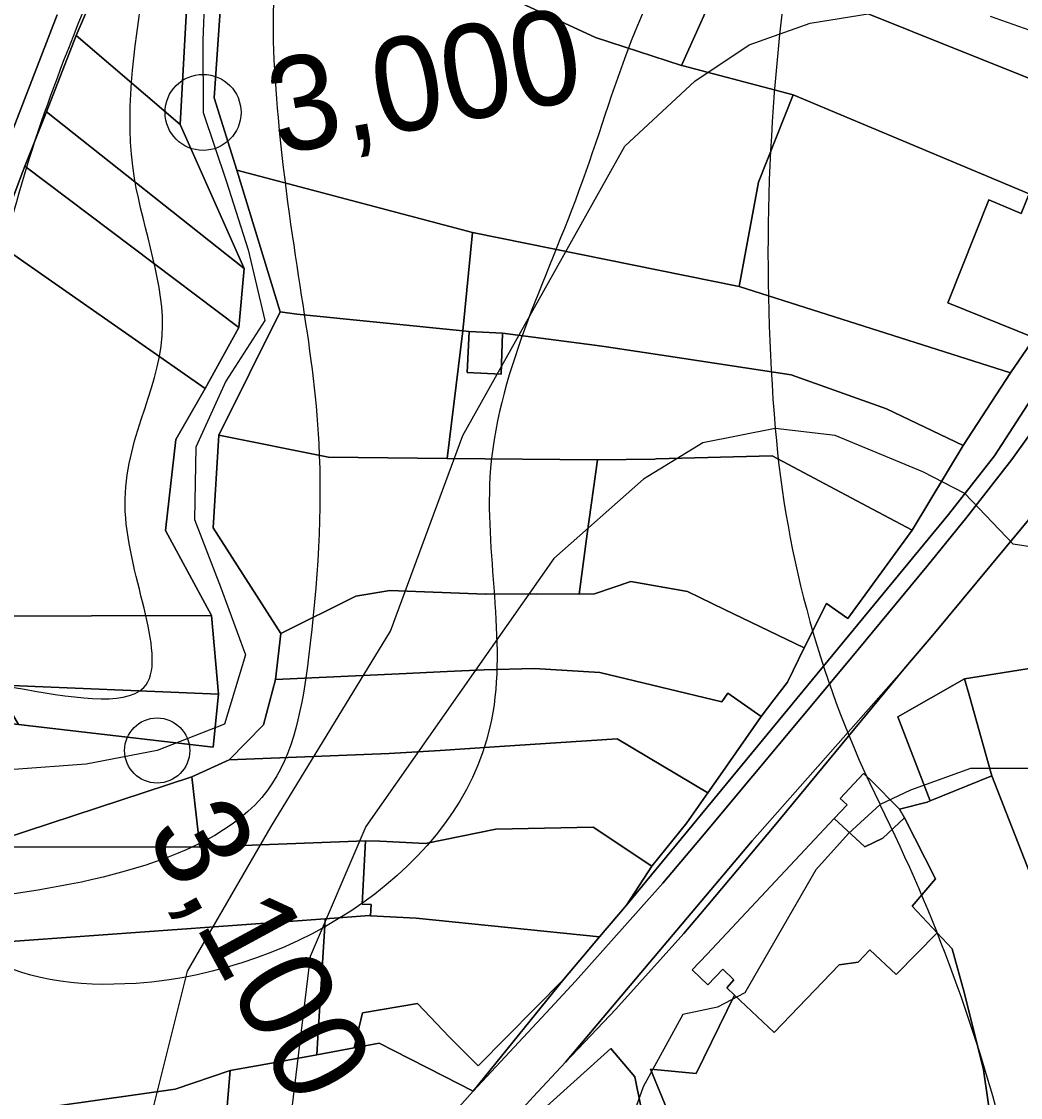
# Model space of a CAD drawing. Extents: x -510989 to -501240, y -1184665 to -1176098.
# Drawn here: x -504823 to -504684.9, y -1182308.5 to -1182159.8 of the extents above; entities that cross this region are included whole.
import ezdxf

# ---------------------------------------------------------------- set-up
doc = ezdxf.new("R2010")
doc.units = 0
for name, color, linetype in [('NAVRH_rozvodnice', 7, 'Continuous'), ('ostatni_plocha_x_draha', 7, 'Continuous'), ('ostatni_plocha_x_neplodna_puda', 7, 'Continuous'), ('ostatni_plocha_x_ostatni_komunikace', 7, 'Continuous'), ('ostatni_plocha_x_silnice', 7, 'Continuous'), ('STAV_zaplavove_uzemi', 7, 'Continuous'), ('trasovani_toku', 7, 'Continuous'), ('trvaly_travni_porost', 7, 'Continuous'), ('vodni_plocha_x_vodni_tok_v_koryt_prir_n_upr', 7, 'Continuous'), ('vrstevnice_01', 7, 'Continuous'), ('vrstevnice_02', 7, 'Continuous'), ('zahrada', 7, 'Continuous'), ('zastavena_plocha_a_nadvori', 7, 'Continuous')]:
    doc.layers.add(name, color=color, linetype=linetype)

msp = doc.modelspace()

# ---------------------------------------------------------------- linework, layer by layer
at = {"layer": 'NAVRH_rozvodnice'}
for centre, radius, start, end in [((-504430.33, -1182191.97), 289.48, 159.1879, 184.7617), ((-504575.51, -1182204.06), 143.79, 184.7617, 206.4002), ((-504915.08, -1182372.63), 235.31, 13.925, 26.4002)]:
    msp.add_arc(centre, radius, start, end, dxfattribs=at)
at = {"layer": 'ostatni_plocha_x_draha'}
msp.add_lwpolyline([(-504818.09, -1182158.83), (-504829.87, -1182189.28), (-504837.58, -1182231.95), (-504833.33, -1182254.08), (-504832.95, -1182255.81), (-504828.96, -1182273.83), (-504828.71, -1182274.97), (-504833.19, -1182275.82), (-504832.22, -1182287.45), (-504829.16, -1182311.19), (-504827.78, -1182318.57), (-504818.47, -1182369.92), (-504825.21, -1182377.61), (-504825.27, -1182384.49), (-504825.8, -1182395.57), (-504822.32, -1182398.72), (-504811.75, -1182408.26), (-504817.08, -1182415.24), (-504816.58, -1182438.27), (-504816.44, -1182444.56), (-504814.64, -1182480.22)], dxfattribs=at)
at = {"layer": 'ostatni_plocha_x_neplodna_puda'}
msp.add_lwpolyline([(-504694.34, -1182287.92), (-504692.64, -1182294.12), (-504690.01, -1182304.64), (-504686.8, -1182326.98), (-504702.57, -1182329.09), (-504718.84, -1182331.27), (-504724.73, -1182332.06), (-504736.04, -1182304.55), (-504729.74, -1182305.15), (-504724.43, -1182294.34), (-504718.94, -1182299.49), (-504709.99, -1182290.13), (-504707.35, -1182289.77), (-504705.71, -1182288.06), (-504702.09, -1182291.48), (-504696.41, -1182285.71)], close=True, dxfattribs=at)
at = {"layer": 'ostatni_plocha_x_ostatni_komunikace'}
for points in [[(-504804.88, -1182137.1), (-504815.47, -1182161.68), (-504819.56, -1182172.23), (-504822.57, -1182179.77), (-504826.57, -1182190.32), (-504832.12, -1182217.73), (-504833.01, -1182222.27), (-504830, -1182241.97), (-504826.67, -1182251.43), (-504823.42, -1182256.92), (-504832.95, -1182255.81), (-504833.33, -1182254.08), (-504837.58, -1182231.95), (-504829.87, -1182189.28), (-504818.09, -1182158.83)], [(-504683.43, -1182211.95), (-504688.49, -1182219.81), (-504694.87, -1182227.88), (-504739.37, -1182281.88), (-504735.89, -1182276.48), (-504731.02, -1182270.51), (-504728.15, -1182266.37), (-504726.37, -1182263.87), (-504720.77, -1182255.81), (-504719, -1182253.51), (-504717.1, -1182251.06), (-504714.82, -1182246.33), (-504711.74, -1182240.21), (-504708.78, -1182242.26), (-504699.89, -1182230.04), (-504692.84, -1182218.37), (-504686.3, -1182208.31), (-504682.98, -1182203.49)], [(-504756.37, -1182312.89), (-504752.28, -1182308.37), (-504747.79, -1182303.57), (-504740.85, -1182296.26), (-504731.46, -1182285.8), (-504728.12, -1182281.9), (-504718.97, -1182270.95), (-504701.01, -1182249.26), (-504697.03, -1182244.56), (-504682.84, -1182227.46)], [(-504678.47, -1182248.35), (-504692.63, -1182250.62), (-504701.87, -1182255.88), (-504697.4, -1182267.48), (-504697.8, -1182267.64), (-504701.61, -1182268.61), (-504705.64, -1182264.56), (-504706.59, -1182263.67), (-504709.82, -1182267.13), (-504708.87, -1182268.02), (-504710.64, -1182269.92), (-504728.23, -1182288.67), (-504730.28, -1182290.81), (-504728.12, -1182292.89), (-504726.04, -1182290.73), (-504724.53, -1182292.19), (-504725.5, -1182293.33), (-504724.43, -1182294.34), (-504729.74, -1182305.15), (-504736.04, -1182304.55), (-504724.73, -1182332.06)], [(-504735.83, -1182317.48), (-504738.22, -1182305.62), (-504741.53, -1182301.68), (-504750.38, -1182309.69)]]:
    msp.add_lwpolyline(points, dxfattribs=at)
at = {"layer": 'ostatni_plocha_x_silnice'}
for points in [[(-504766.11, -1182313.77), (-504760.55, -1182307.61), (-504749.86, -1182296.14), (-504746.43, -1182292.4), (-504737.71, -1182282.64), (-504734.35, -1182278.85), (-504728.65, -1182272.06), (-504708.46, -1182247.87), (-504697.85, -1182235.08), (-504692.31, -1182228.28), (-504686.08, -1182220.29), (-504681.44, -1182213.79), (-504676.25, -1182205.38), (-504672.53, -1182198), (-504670.11, -1182192.37), (-504668.31, -1182187.63), (-504666.07, -1182180.74), (-504664.83, -1182175.8), (-504663.05, -1182167.12), (-504660.74, -1182161.27), (-504660.37, -1182149.27)], [(-504654.43, -1182155.52), (-504655.64, -1182163.51), (-504656.9, -1182170.57), (-504658.17, -1182176.68), (-504659.83, -1182183.78), (-504669.04, -1182203.7), (-504682.84, -1182227.46), (-504697.03, -1182244.56), (-504701.01, -1182249.26), (-504722, -1182272.99), (-504747.79, -1182303.57), (-504752.28, -1182308.37), (-504756.37, -1182312.89)], [(-504681.44, -1182213.79), (-504686.08, -1182220.29), (-504692.31, -1182228.28), (-504697.85, -1182235.08), (-504708.46, -1182247.87), (-504728.65, -1182272.06), (-504734.35, -1182278.85), (-504737.71, -1182282.64), (-504746.43, -1182292.4), (-504749.86, -1182296.14), (-504760.55, -1182307.61), (-504748.02, -1182292.13), (-504743.1, -1182286.27), (-504739.37, -1182281.88), (-504694.87, -1182227.88), (-504688.49, -1182219.81), (-504683.43, -1182211.95)]]:
    msp.add_lwpolyline(points, dxfattribs=at)
msp.add_lwpolyline([(-504701.01, -1182249.26), (-504718.97, -1182270.95), (-504728.12, -1182281.9), (-504731.46, -1182285.8), (-504740.85, -1182296.26), (-504747.79, -1182303.57), (-504722, -1182272.99)], close=True, dxfattribs=at)
at = {"layer": 'STAV_zaplavove_uzemi'}
for points in [[(-504826.46, -1182247.73), (-504827.62, -1182204.68), (-504817.15, -1182165.12), (-504791.55, -1182113.93), (-504727.56, -1182034.81), (-504708.94, -1182017.35), (-504669.38, -1181991.76), (-504649.6, -1181961.5), (-504628.66, -1181917.29), (-504601.9, -1181867.26), (-504597.24, -1181809.08), (-504585.16, -1181766.79), (-504596.8, -1181741.4), (-504604.2, -1181726.59), (-504633.82, -1181658.9), (-504646.51, -1181600.72), (-504660.26, -1181556.29), (-504751.04, -1181459.08), (-504798.4, -1181384.84), (-504826.55, -1181347.73), (-504862.39, -1181315.73), (-504866.23, -1181265.81), (-504862.39, -1181205.66), (-504853.43, -1181164.7), (-504793.92, -1181116.47), (-504755.84, -1181064.64), (-504725.17, -1181018.1), (-504649.01, -1180947.23), (-504594, -1180900.69), (-504545.35, -1180879.53), (-504377.38, -1180832.83), (-504317.01, -1180808.36), (-504368.93, -1180802.59), (-504426.63, -1180826.63), (-504542.02, -1180859.32)], [(-504547.82, -1181597.63), (-504529.08, -1181677.7), (-504510.34, -1181762.87), (-504510.34, -1181805.46), (-504503.52, -1181848.05), (-504522.26, -1181902.56), (-504557.31, -1181989.81), (-504582.91, -1182010.28), (-504608.51, -1182029.48), (-504618.75, -1182071.72), (-504632.83, -1182096.04), (-504648.18, -1182115.24), (-504664.82, -1182122.91), (-504685.3, -1182130.59), (-504727.54, -1182144.67), (-504745.46, -1182181.79), (-504758.25, -1182222.75), (-504758.25, -1182257.3), (-504807.19, -1182292.7), (-504828.34, -1182288.47), (-504827.28, -1182244.04)], [(-504574.97, -1181692.93), (-504558.07, -1181754.88), (-504562.29, -1181804.15), (-504563.7, -1181856.24), (-504570.74, -1181913.97), (-504583.41, -1181961.83), (-504617.2, -1182002.66), (-504652.4, -1182051.94), (-504665.07, -1182080.1), (-504696.04, -1182099.81), (-504738.28, -1182108.25), (-504752.36, -1182122.33), (-504767.85, -1182144.86), (-504780.52, -1182142.04), (-504787.55, -1182173.02), (-504781.92, -1182218.07), (-504783.33, -1182247.63), (-504788.96, -1182265.94), (-504808.67, -1182277.2), (-504832.61, -1182281.42)], [(-504824.03, -1182251.79), (-504806.11, -1182251.79), (-504808.67, -1182227.48), (-504803.55, -1182203.16), (-504807.39, -1182181.4), (-504806.11, -1182154.52), (-504795.88, -1182126.36), (-504783.08, -1182119.97), (-504770.28, -1182113.56), (-504754.92, -1182091.81), (-504726.76, -1182079.01), (-504689.64, -1182070.05), (-504667.89, -1182041.89), (-504634.61, -1181997.1), (-504615.41, -1181959.98), (-504602.61, -1181927.98), (-504596.21, -1181880.63), (-504594.68, -1181823.86), (-504583.41, -1181774.59), (-504590.45, -1181740.8), (-504600.31, -1181726.72)]]:
    msp.add_spline(points, degree=3, dxfattribs=at)
at = {"layer": 'trasovani_toku'}
for p, q in [((-504797.57, -1182152.33), (-504797.94, -1182162.32)), ((-504797.94, -1182162.32), (-504797.92, -1182172.32)), ((-504797.92, -1182172.32), (-504794.74, -1182181.8)), ((-504794.74, -1182181.8), (-504791.66, -1182191.32)), ((-504791.66, -1182191.32), (-504789.4, -1182201.06)), ((-504789.4, -1182201.06), (-504794.78, -1182209.49)), ((-504794.78, -1182209.49), (-504798.94, -1182218.58)), ((-504798.94, -1182218.58), (-504799.1, -1182228.58)), ((-504799.1, -1182228.58), (-504795.5, -1182237.91)), ((-504795.5, -1182237.91), (-504792.06, -1182247.3)), ((-504792.06, -1182247.3), (-504794.96, -1182256.87)), ((-504794.96, -1182256.87), (-504804.27, -1182260.52)), ((-504804.27, -1182260.52), (-504814.09, -1182262.41)), ((-504814.09, -1182262.41), (-504824.06, -1182263.12))]:
    msp.add_line(p, q, dxfattribs=at)
for centre, radius in [((-504797.92, -1182172.32), 5.25), ((-504804.27, -1182260.52), 4.5)]:
    msp.add_circle(centre, radius, dxfattribs=at)
at = {"layer": 'trvaly_travni_porost'}
for points in [[(-504793.26, -1182112.23), (-504779.73, -1182122.83), (-504769.89, -1182130.23), (-504782.59, -1182127.22), (-504790.34, -1182129.48), (-504796.78, -1182140.31), (-504799.68, -1182148.82), (-504801.08, -1182173.98), (-504815.47, -1182161.68), (-504804.88, -1182137.1)], [(-504819.56, -1182172.23), (-504815.47, -1182161.68), (-504801.08, -1182173.98), (-504792.25, -1182193.9)], [(-504822.57, -1182179.77), (-504819.56, -1182172.23), (-504792.25, -1182193.9), (-504792.98, -1182202.05)], [(-504826.57, -1182190.32), (-504822.57, -1182179.77), (-504792.98, -1182202.05), (-504797.61, -1182210.46)], [(-504826.57, -1182190.32), (-504797.61, -1182210.46), (-504801.69, -1182217.53), (-504803.1, -1182230.12), (-504796.75, -1182241.85), (-504830, -1182241.97), (-504833.01, -1182222.27), (-504832.12, -1182217.73)], [(-504830, -1182241.97), (-504796.75, -1182241.85), (-504795.78, -1182252.73), (-504826.67, -1182251.43)], [(-504795.78, -1182252.73), (-504796.53, -1182260.05), (-504823.42, -1182256.92), (-504826.67, -1182251.43)]]:
    msp.add_lwpolyline(points, close=True, dxfattribs=at)
at = {"layer": 'vodni_plocha_x_vodni_tok_v_koryt_prir_n_upr'}
msp.add_lwpolyline([(-504794.87, -1182148.24), (-504796.39, -1182170.3), (-504793.27, -1182180.29), (-504787.25, -1182199.87), (-504795.75, -1182216.93), (-504796.5, -1182229.75), (-504787.17, -1182244.36), (-504787.92, -1182250.71), (-504789.54, -1182256.96), (-504794.33, -1182261.82), (-504799.48, -1182264.16), (-504828.96, -1182273.83), (-504832.95, -1182255.81), (-504823.42, -1182256.92), (-504796.53, -1182260.05), (-504795.78, -1182252.73), (-504796.75, -1182241.85), (-504803.1, -1182230.12), (-504801.69, -1182217.53), (-504797.61, -1182210.46), (-504792.98, -1182202.05), (-504792.25, -1182193.9), (-504801.08, -1182173.98), (-504799.68, -1182148.82)], dxfattribs=at)
at = {"layer": 'vrstevnice_01'}
msp.add_lwpolyline([(-504613, -1182249), (-504624, -1182240), (-504631.5, -1182236), (-504635.5, -1182235), (-504645.59, -1182237), (-504660, -1182236), (-504685.91, -1182232), (-504692.59, -1182225), (-504698.41, -1182222), (-504710.5, -1182217), (-504718.81, -1182216), (-504728.81, -1182218), (-504737, -1182223), (-504749.41, -1182234), (-504775.41, -1182271), (-504783.09, -1182289), (-504788.69, -1182335)], dxfattribs=at)
at = {"layer": 'vrstevnice_02'}
for points in [[(-504689.09, -1182159), (-504675, -1182164), (-504667.91, -1182167), (-504658.19, -1182176), (-504647.91, -1182178), (-504643.5, -1182184), (-504639.81, -1182187), (-504633.81, -1182189), (-504629.69, -1182188), (-504624.81, -1182186), (-504617.81, -1182180), (-504614.31, -1182172), (-504610.69, -1182153)], [(-504823.59, -1182345), (-504819.91, -1182358), (-504818.59, -1182360), (-504816.59, -1182361), (-504814, -1182361), (-504811.41, -1182357), (-504808.41, -1182347), (-504805.81, -1182325), (-504805.31, -1182312), (-504800.09, -1182291), (-504788.5, -1182271), (-504772, -1182244), (-504762, -1182217), (-504739.59, -1182177), (-504729.91, -1182168), (-504722.41, -1182163), (-504714, -1182160), (-504701.69, -1182158)], [(-504602.41, -1182291), (-504623.69, -1182274), (-504627.81, -1182274), (-504633.19, -1182275), (-504635.69, -1182275), (-504675.5, -1182263), (-504691.81, -1182263), (-504700.09, -1182266), (-504704.31, -1182268), (-504708.69, -1182272), (-504713.19, -1182277), (-504723, -1182294), (-504726.81, -1182296), (-504731.59, -1182297), (-504737.09, -1182307), (-504738.5, -1182311), (-504739.41, -1182328)]]:
    msp.add_lwpolyline(points, dxfattribs=at)
at = {"layer": 'zahrada'}
for points in [[(-504783.29, -1182133.37), (-504777.16, -1182133.05), (-504769.3, -1182135.01), (-504736.9, -1182149.9), (-504726, -1182152.98), (-504731.77, -1182165.83), (-504743.64, -1182161.96), (-504791.97, -1182139.62), (-504787.17, -1182134.66)], [(-504791.97, -1182139.62), (-504743.64, -1182161.96), (-504731.77, -1182165.83), (-504731.55, -1182165.9), (-504716.35, -1182169.88), (-504721.13, -1182181.96), (-504723.8, -1182196.37), (-504760.65, -1182188.91), (-504793.27, -1182180.29), (-504796.39, -1182170.3), (-504794.87, -1182148.24)], [(-504793.27, -1182180.29), (-504760.65, -1182188.91), (-504762, -1182202.53), (-504784.94, -1182200.19), (-504787.25, -1182199.87)], [(-504723.8, -1182196.37), (-504686.3, -1182208.31), (-504692.84, -1182218.37), (-504703.44, -1182213.28), (-504716.62, -1182208.58), (-504733.56, -1182206.02), (-504742.16, -1182204.72), (-504743.78, -1182204.47), (-504756.51, -1182202.84), (-504761.12, -1182202.62), (-504762, -1182202.53), (-504760.65, -1182188.91)], [(-504787.25, -1182199.87), (-504784.94, -1182200.19), (-504762, -1182202.53), (-504764.17, -1182220.16), (-504780.58, -1182219.97), (-504795.75, -1182216.93)], [(-504780.58, -1182219.97), (-504764.17, -1182220.16), (-504743.38, -1182220.33), (-504744.79, -1182230.59), (-504745.93, -1182238.92), (-504751.83, -1182238.86), (-504758.81, -1182238.89), (-504758.87, -1182238.89), (-504772.09, -1182238.39), (-504776.79, -1182239.17), (-504787.17, -1182244.36), (-504796.5, -1182229.75), (-504795.75, -1182216.93)], [(-504692.63, -1182250.62), (-504691.95, -1182253.01), (-504689.35, -1182262.23), (-504688.84, -1182264.02), (-504697.4, -1182267.48), (-504701.87, -1182255.88)], [(-504799.48, -1182264.16), (-504798.37, -1182273.87), (-504828.96, -1182273.83)], [(-504798.37, -1182273.87), (-504775.44, -1182273.01), (-504775.91, -1182281.73), (-504774.69, -1182281.81), (-504774.78, -1182283.35), (-504774.92, -1182283.34), (-504781.03, -1182283.8), (-504832.22, -1182287.45), (-504833.19, -1182275.82), (-504828.71, -1182274.97), (-504828.96, -1182273.83)], [(-504781.09, -1182284.77), (-504782.03, -1182300.18), (-504782.18, -1182302.56), (-504788.44, -1182303.71), (-504794.15, -1182304.76), (-504801.77, -1182307.31), (-504829.16, -1182311.19), (-504832.22, -1182287.45), (-504781.03, -1182283.8)], [(-504775.89, -1182296.77), (-504768.25, -1182295.47), (-504763.85, -1182300.14), (-504759.88, -1182304.08), (-504748.02, -1182292.13), (-504760.55, -1182307.61), (-504764.65, -1182305.53), (-504771.6, -1182301.99), (-504773.58, -1182300.98), (-504777.03, -1182301.61)], [(-504794.15, -1182304.76), (-504794.69, -1182310.8), (-504795.82, -1182316.65), (-504810.79, -1182317.05), (-504827.78, -1182318.57), (-504829.16, -1182311.19), (-504801.77, -1182307.31)]]:
    msp.add_lwpolyline(points, close=True, dxfattribs=at)
at = {"layer": 'zastavena_plocha_a_nadvori'}
for points in [[(-504711.71, -1182141.93), (-504701.67, -1182146.31), (-504695.74, -1182148.63), (-504695.54, -1182148.01), (-504687.85, -1182150.74), (-504687.76, -1182150.51), (-504687.55, -1182149.95), (-504668.12, -1182157.54), (-504668.31, -1182158.11), (-504666.96, -1182158.74), (-504666.17, -1182159.11), (-504668.4, -1182164.75), (-504669.53, -1182164.28), (-504672.79, -1182171.96), (-504694, -1182163.49), (-504705.94, -1182158.72), (-504715.12, -1182155.48), (-504715.65, -1182155.38)], [(-504726, -1182152.98), (-504715.65, -1182155.38), (-504715.12, -1182155.48), (-504705.94, -1182158.72), (-504694, -1182163.49), (-504672.79, -1182171.96), (-504676.92, -1182181.68), (-504678.6, -1182185.63), (-504683.69, -1182183.57), (-504716.35, -1182169.88), (-504731.55, -1182165.9), (-504731.77, -1182165.83)], [(-504721.13, -1182181.96), (-504716.35, -1182169.88), (-504683.69, -1182183.57), (-504684.8, -1182186.31), (-504689.28, -1182184.41), (-504694.94, -1182198.66), (-504682.98, -1182203.49), (-504686.3, -1182208.31), (-504723.8, -1182196.37)], [(-504683.69, -1182183.57), (-504678.6, -1182185.63), (-504676.16, -1182186.61), (-504682.98, -1182203.49), (-504694.94, -1182198.66), (-504689.28, -1182184.41), (-504684.8, -1182186.31)], [(-504762, -1182202.53), (-504761.12, -1182202.62), (-504761.39, -1182208.25), (-504756.71, -1182208.48), (-504756.51, -1182202.84), (-504743.78, -1182204.47), (-504742.16, -1182204.72), (-504733.56, -1182206.02), (-504716.62, -1182208.58), (-504703.44, -1182213.28), (-504692.84, -1182218.37), (-504699.89, -1182230.04), (-504705.34, -1182227.16), (-504719.22, -1182219.81), (-504735.25, -1182220.22), (-504735.45, -1182220.23), (-504743.38, -1182220.33), (-504764.17, -1182220.16)], [(-504761.12, -1182202.62), (-504756.51, -1182202.84), (-504756.71, -1182208.48), (-504761.39, -1182208.25)], [(-504735.25, -1182220.22), (-504719.22, -1182219.81), (-504705.34, -1182227.16), (-504699.89, -1182230.04), (-504708.78, -1182242.26), (-504711.74, -1182240.21), (-504714.82, -1182246.33), (-504725.84, -1182241.01), (-504730.94, -1182238.55), (-504738.79, -1182237.16), (-504743.78, -1182238.88), (-504745.93, -1182238.92), (-504744.79, -1182230.59), (-504743.38, -1182220.33), (-504735.45, -1182220.23)], [(-504738.79, -1182237.16), (-504730.94, -1182238.55), (-504725.84, -1182241.01), (-504714.82, -1182246.33), (-504717.1, -1182251.06), (-504719, -1182253.51), (-504720.77, -1182255.81), (-504725.37, -1182252.61), (-504726.2, -1182253.8), (-504743.06, -1182249.74), (-504752.11, -1182249.19), (-504759.03, -1182249.35), (-504764.18, -1182249.59), (-504770.8, -1182249.9), (-504787.92, -1182250.71), (-504787.17, -1182244.36), (-504776.79, -1182239.17), (-504772.09, -1182238.39), (-504758.87, -1182238.89), (-504758.81, -1182238.89), (-504751.83, -1182238.86), (-504745.93, -1182238.92), (-504743.78, -1182238.88)], [(-504678.47, -1182248.35), (-504677.55, -1182251.26), (-504668.96, -1182277.25), (-504670.23, -1182277.56), (-504676.03, -1182278.97), (-504682.43, -1182280.53), (-504688.84, -1182264.02), (-504689.35, -1182262.23), (-504691.95, -1182253.01), (-504692.63, -1182250.62)], [(-504752.11, -1182249.19), (-504743.06, -1182249.74), (-504726.2, -1182253.8), (-504725.37, -1182252.61), (-504720.77, -1182255.81), (-504726.37, -1182263.87), (-504728.15, -1182266.37), (-504740.66, -1182258.88), (-504756.94, -1182259.97), (-504765.14, -1182260.5), (-504772.18, -1182260.93), (-504794.33, -1182261.82), (-504789.54, -1182256.96), (-504787.92, -1182250.71), (-504770.8, -1182249.9), (-504764.18, -1182249.59), (-504759.03, -1182249.35)], [(-504756.94, -1182259.97), (-504740.66, -1182258.88), (-504728.15, -1182266.37), (-504731.02, -1182270.51), (-504735.89, -1182276.48), (-504743.97, -1182271.12), (-504757.42, -1182271.37), (-504767.15, -1182273.37), (-504773.46, -1182273.03), (-504775.44, -1182273.01), (-504798.37, -1182273.87), (-504799.48, -1182264.16), (-504794.33, -1182261.82), (-504772.18, -1182260.93), (-504765.14, -1182260.5)], [(-504706.59, -1182263.67), (-504705.64, -1182264.56), (-504701.61, -1182268.61), (-504700.94, -1182269.81), (-504703.91, -1182272.64), (-504706.44, -1182273.85), (-504710.64, -1182269.92), (-504708.87, -1182268.02), (-504709.82, -1182267.13)], [(-504697.4, -1182267.48), (-504688.84, -1182264.02), (-504682.43, -1182280.53), (-504678.79, -1182289.89), (-504677.14, -1182321.18), (-504672.44, -1182341.25), (-504670.44, -1182348.03), (-504672.29, -1182348.47), (-504682.24, -1182350.8), (-504686.8, -1182326.98), (-504690.01, -1182304.64), (-504692.64, -1182294.12), (-504694.34, -1182287.92), (-504696.41, -1182285.71), (-504699.87, -1182282.02), (-504696.65, -1182278.27), (-504700.94, -1182269.81), (-504701.61, -1182268.61), (-504697.8, -1182267.64)], [(-504757.42, -1182271.37), (-504743.97, -1182271.12), (-504735.89, -1182276.48), (-504739.37, -1182281.88), (-504743.1, -1182286.27), (-504768.46, -1182283.71), (-504774.78, -1182283.35), (-504774.69, -1182281.81), (-504775.91, -1182281.73), (-504775.44, -1182273.01), (-504773.46, -1182273.03), (-504767.15, -1182273.37)], [(-504703.91, -1182272.64), (-504700.94, -1182269.81), (-504696.65, -1182278.27), (-504699.87, -1182282.02), (-504696.41, -1182285.71), (-504702.09, -1182291.48), (-504705.71, -1182288.06), (-504707.35, -1182289.77), (-504709.99, -1182290.13), (-504718.94, -1182299.49), (-504724.43, -1182294.34), (-504725.5, -1182293.33), (-504724.53, -1182292.19), (-504726.04, -1182290.73), (-504728.12, -1182292.89), (-504730.28, -1182290.81), (-504728.23, -1182288.67), (-504710.64, -1182269.92), (-504706.44, -1182273.85)], [(-504774.78, -1182283.35), (-504768.46, -1182283.71), (-504743.1, -1182286.27), (-504748.02, -1182292.13), (-504759.88, -1182304.08), (-504763.85, -1182300.14), (-504768.25, -1182295.47), (-504775.89, -1182296.77), (-504777.03, -1182301.61), (-504782.18, -1182302.56), (-504782.03, -1182300.18), (-504781.09, -1182284.77), (-504781.03, -1182283.8), (-504774.92, -1182283.34)], [(-504773.58, -1182300.98), (-504771.6, -1182301.99), (-504764.65, -1182305.53), (-504760.55, -1182307.61), (-504766.11, -1182313.77), (-504772.74, -1182321.46), (-504776.92, -1182319.14), (-504783.84, -1182314.56), (-504794.69, -1182310.8), (-504794.15, -1182304.76), (-504788.44, -1182303.71), (-504782.18, -1182302.56), (-504777.03, -1182301.61)], [(-504738.22, -1182305.62), (-504735.83, -1182317.48), (-504742.13, -1182319.1), (-504746.2, -1182320.15), (-504746.89, -1182313.54), (-504748.57, -1182311.68), (-504750.38, -1182309.69), (-504741.53, -1182301.68)]]:
    msp.add_lwpolyline(points, close=True, dxfattribs=at)

# ---------------------------------------------------------------- texts
at = {"layer": 'trasovani_toku'}
for s, rotation, p in [('3,000', 10.3091, (-504787.59, -1182178.17)), ('3,100', 298.4855, (-504806.01, -1182271.85))]:
    msp.add_text(s, height=13, rotation=rotation, dxfattribs=at).set_placement(p)

doc.saveas('drawing.dxf')
